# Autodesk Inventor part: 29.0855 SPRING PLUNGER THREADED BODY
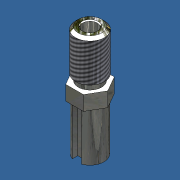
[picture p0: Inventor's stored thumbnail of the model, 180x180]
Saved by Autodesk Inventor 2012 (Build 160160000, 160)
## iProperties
Created: 2016-09
Part Number: 29.0855 SPRING PLUNGER THREADED BODY
Material: Default
Document SubType Name: Modeling
Designer: Admin
Density: 1 g/cm^3
Author: Admin
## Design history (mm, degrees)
feature "Base1"
sketch "Sketch1"
  geometry: L1 (-9.815, 0)-(-4.907, 8.5); L2 (-4.907, 8.5)-(4.907, 8.5); L3 (4.907, 8.5)-(9.815, 0); L4 (9.815, 0)-(4.907, -8.5); L5 (4.907, -8.5)-(-4.907, -8.5); L6 (-4.907, -8.5)-(-9.815, 0); C1 r 8.5 at (0, 0) reference; 2 further points
  constraints: 12 end point, 5 equal length, 2 horizontal, 2 horizontal alignment, 2 midpoint, 2 vertical alignment
  dimensions: "d0" = 120 deg angle of L1 L2; "d1" = 120 deg angle of L3 L2 (derived); "d2" = 120 deg angle of L6 L1 (derived); "d3" = 120 deg angle of L5 L6 (derived); "d4" = 120 deg angle of L4 L5 (derived); "d5" = 120 deg angle of L4 L3 (derived); "d6" = 17 distance between parallel lines of L5 L2
extrude "Extrusion1" join sketch "Sketch1" distance "d7" = 8; taper "d8" = 0 deg
sketch "Sketch2"
  geometry: L1 (7.361, 4.25)-(4.907, 8.5) reference; L2 (4.907, 8.5)-(0, 8.5) reference; C1 r 9 at (0, 0) reference; C2 r 17.72 at (0, 0); C3 r 7.675 at (0, 0); A1 r 8.5 centre (0, 0) between (7.361, 4.25) and (0, 8.5) reference
  constraints: 2 centre point, 2 coincident
  dimensions: "d9" = 15.35 diameter of C3
extrude "Extrusion2" cut sketch "Sketch2" distance "d10" = 76.2; taper "d11" = 0 deg
workplane "Work Plane1"
sketch "Sketch3"
  geometry: C1 r 7.675 at (0, 0) reference; 2 further points
extrude "Extrusion3" cut sketch "Sketch3" distance "d13" = 76.2; taper "d14" = 0 deg
sketch "Sketch6"
  geometry: C1 r 4 at (0, 0) reference
extrude "Extrusion5" cut sketch "Sketch6" stored distance "d17" = 10; taper "d18" = 0 deg
workplane "Work Plane2"
sketch "Sketch7"
  geometry: C1 r 8 at (0, 0) reference; C2 r 4 at (0, 0) reference; 1 further point
extrude "Extrusion6" join sketch "Sketch7" distance "d20" = 10; taper "d21" = 0 deg
sketch "Sketch8"
  geometry: L1 (4.907, 8.5)-(-4.907, 8.5) reference; L2 (2.5, 8.5)-(-2.5, 8.5); L3 (-2.5, 8.5)-(-2.5, 4.25); L4 (-2.5, 4.25)-(2.5, 4.25); L5 (2.5, 4.25)-(2.5, 8.5); C1 r 4 at (0, 0) reference; 1 further point
  constraints: 8 end point, 2 parallel, 1 horizontal, 1 midpoint, 1 perpendicular, 1 point on line, 1 vertical alignment
  dimensions: "d22" = 4.25 distance of L2.end L3.end; "d23" = 5 distance of L3.end L4.end
extrude "Extrusion7" cut sketch "Sketch8" stored distance "d24" = 10; taper "d25" = 0 deg
body "Solid1"
node "Projected Loop1"
other parameters: "d12" = 26.9875, "d19" = 3.5
